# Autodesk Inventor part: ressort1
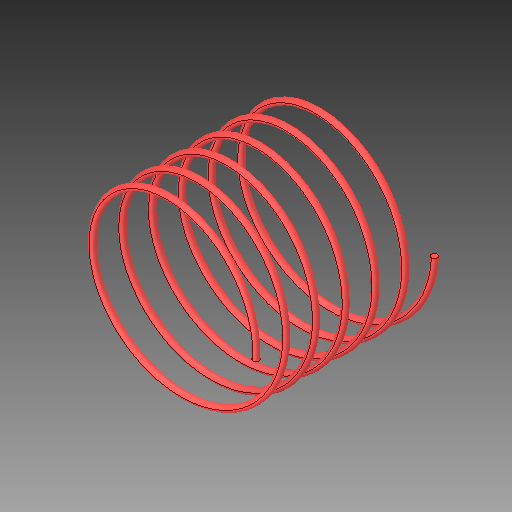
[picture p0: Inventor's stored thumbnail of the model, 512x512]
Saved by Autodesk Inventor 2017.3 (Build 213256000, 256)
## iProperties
Created: 2007-11
Part Number: ressort1
Material: Générique
Document SubType Name: Modeling
Designer: ficho
Density: 1 g/cm^3
Appearance: Par défaut
Author: ficho
Sending System: SolidWorks 2009
Last Author: christophe
Last Saved: 2011-02-10
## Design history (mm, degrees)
feature "Balayage1"
node "Solide1"
